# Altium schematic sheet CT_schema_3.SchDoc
size 284 x 135 mm
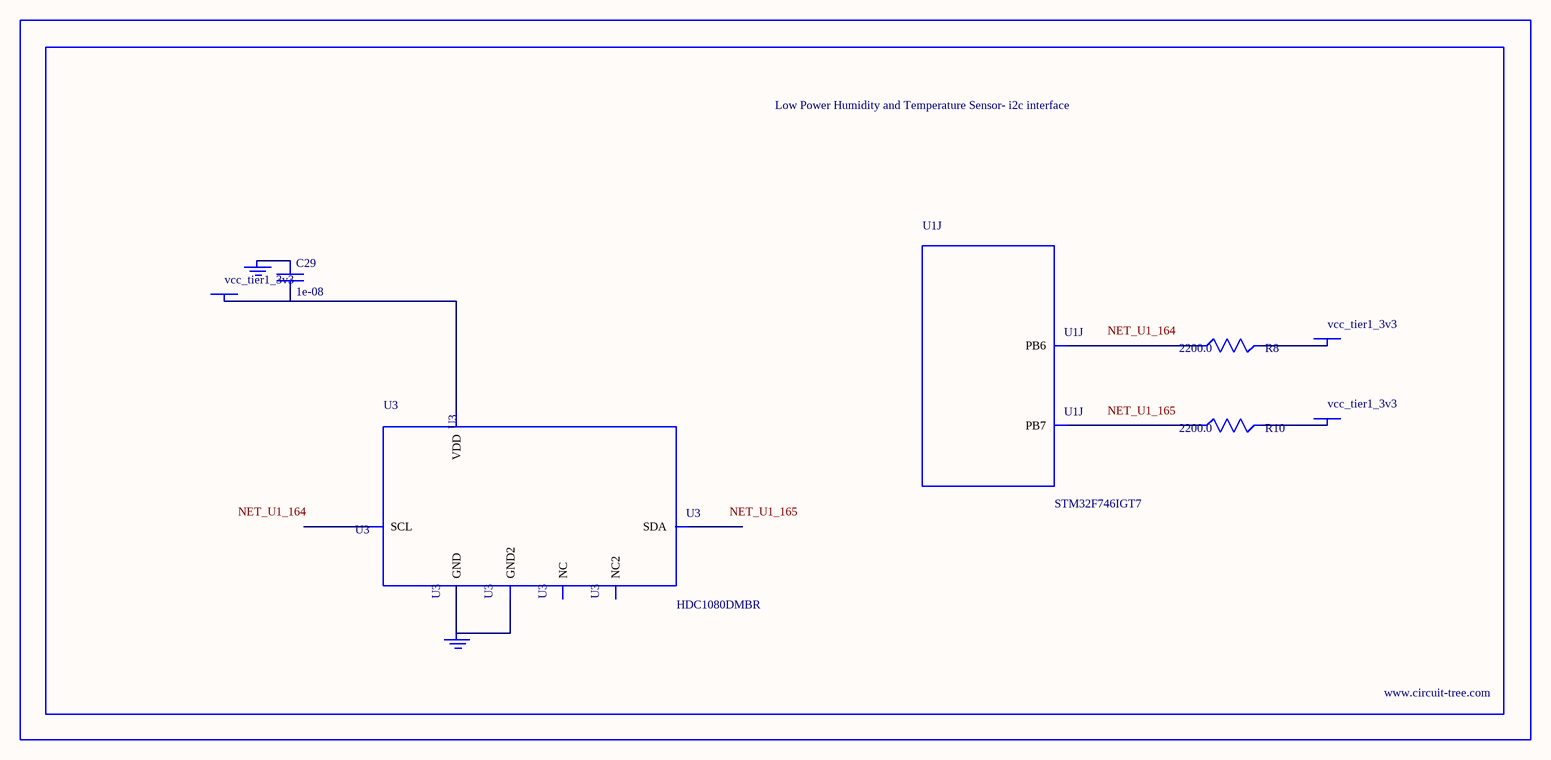
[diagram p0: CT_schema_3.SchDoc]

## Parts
BORDER2  (no value)
C29  1e-08  [C0402]
GND_INSTANCE_2_0  (no value)
GND_INSTANCE_2_1  (no value)
POWER_INSTANCE_2_0  vcc_tier1_3v3
POWER_INSTANCE_2_1  vcc_tier1_3v3
POWER_INSTANCE_2_2  vcc_tier1_3v3
R8  2200.0  [R0603]
R10  2200.0  [R0603]
U1  STM32F746IGT7  [LQFP176]  (part J of 15)
U3  HDC1080DMBR  [WSON-6]

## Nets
NetC29_1: C29.1 GND_INSTANCE_2_0.0(GND)
NetC29_2: C29.2 POWER_INSTANCE_2_0.0(PWR) U3.5(VDD)
NetGND_INSTANCE_2_1_0: GND_INSTANCE_2_1.0(GND) U3.2(GND) U3.PAD(GND2)
NetPOWER_INSTANCE_2_1_0: POWER_INSTANCE_2_1.0(PWR) R8.2
NetPOWER_INSTANCE_2_2_0: POWER_INSTANCE_2_2.0(PWR) R10.2
NetR8_1: R8.1 U1.164(PB6)
NetR10_1: R10.1 U1.165(PB7)

Not connected (* = marked no-connect by the designer): U3 1(SDA) 3(NC) 4(NC2) 6(SCL)

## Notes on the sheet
- Labels drawn without touching a wire or pin: NET_U1_164, NET_U1_165

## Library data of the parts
BORDER2 = BORDER_PAGE2
C29 = C0402C103K3RAC
GND_INSTANCE_2_0 GND_INSTANCE_2_1 = GND
POWER_INSTANCE_2_0-POWER_INSTANCE_2_2 = PWR
R8 R10 = RC0603JR-072K2L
